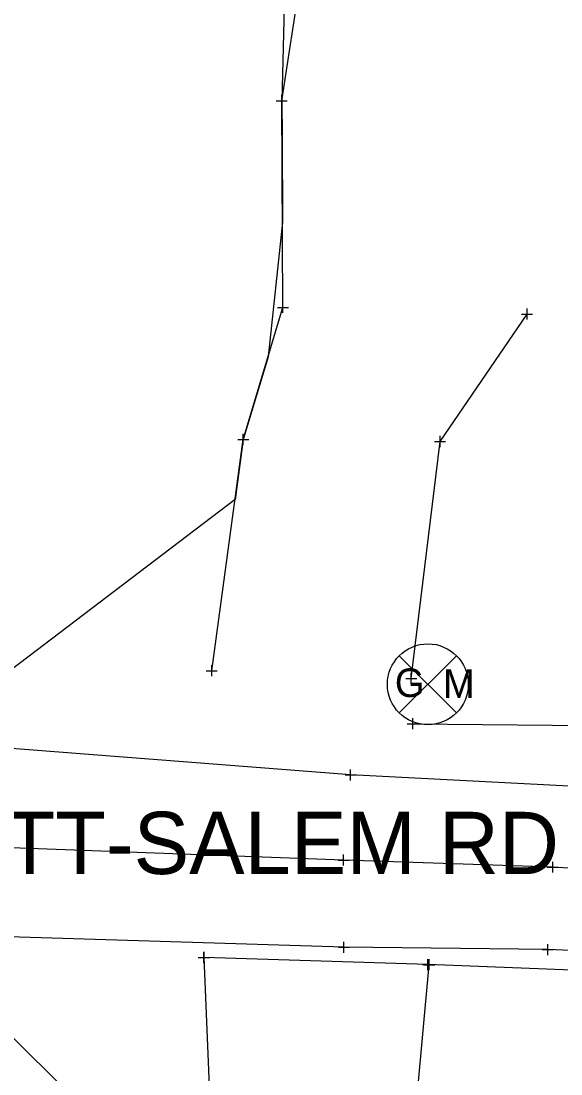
# Model space of a CAD drawing. Extents: x -1 to 1157254, y -1 to 2021979.
# Drawn here: x 1150264.3 to 1150326.7, y 2020191.5 to 2020313.4 of the extents above; entities that cross this region are included whole.
import ezdxf

# ---------------------------------------------------------------- set-up
doc = ezdxf.new("R2010")
doc.units = 0
for name, color, linetype in [('S_BUILDING_ANNOT', 7, 'Continuous'), ('S_CAL_CORNER_ANNOT', 7, 'Continuous'), ('S_CTL_TABLE', 7, 'Continuous'), ('S_DRIVEWAY_ANNOT', 7, 'Continuous'), ('S_EDGE_BITUMINOUS_ANNOT', 7, 'Continuous'), ('S_EDGE_CONCRETE', 7, 'Continuous'), ('S_EDGE_CONCRETE_ANNOT', 7, 'Continuous'), ('S_GAS_PUMP_ISLAND_ANNOT', 7, 'Continuous'), ('S_GATE', 7, 'Continuous')]:
    doc.layers.add(name, color=color, linetype=linetype)

msp = doc.modelspace()

# ---------------------------------------------------------------- linework, layer by layer
at = {"layer": 'S_BUILDING_ANNOT'}
for p, q in [((1150309.59, 2020231.42), (1150309.59, 2020232.69)), ((1150308.96, 2020232.06), (1150310.23, 2020232.06)), ((1150309.59, 2020232.06), (1150309.59, 2020232.06)), ((1150301.77, 2020226.14), (1150303.04, 2020226.14)), ((1150302.4, 2020225.5), (1150302.4, 2020226.77)), ((1150302.4, 2020226.14), (1150302.4, 2020226.14)), ((1150301.59, 2020215.63), (1150301.59, 2020216.91)), ((1150300.95, 2020216.27), (1150302.23, 2020216.27)), ((1150301.59, 2020216.27), (1150301.59, 2020216.27)), ((1150325.15, 2020215.45), (1150326.42, 2020215.46)), ((1150325.79, 2020214.82), (1150325.79, 2020216.09)), ((1150325.79, 2020215.45), (1150325.79, 2020215.45)), ((1150301.63, 2020205.55), (1150301.63, 2020206.82)), ((1150301, 2020206.19), (1150302.27, 2020206.19)), ((1150301.63, 2020206.19), (1150301.63, 2020206.19)), ((1150324.58, 2020205.91), (1150325.86, 2020205.91)), ((1150325.22, 2020205.27), (1150325.22, 2020206.55)), ((1150325.22, 2020205.91), (1150325.22, 2020205.91))]:
    msp.add_line(p, q, dxfattribs=at)
at = {"layer": 'S_CAL_CORNER_ANNOT'}
for p, q in [((1150308.03, 2020233.31), (1150314.65, 2020239.92)), ((1150308.03, 2020239.92), (1150314.65, 2020233.31))]:
    msp.add_line(p, q, dxfattribs=at)
msp.add_circle((1150311.34, 2020236.62), 4.68, dxfattribs=at)
at = {"layer": 'S_CTL_TABLE'}
for p, q in [((1150293.8, 2020304.15), (1150295.07, 2020304.15)), ((1150294.44, 2020303.52), (1150294.43, 2020304.79)), ((1150294.44, 2020304.15), (1150294.44, 2020304.15)), ((1150293.92, 2020280.24), (1150295.2, 2020280.24)), ((1150294.56, 2020279.6), (1150294.56, 2020280.87)), ((1150294.56, 2020280.24), (1150294.56, 2020280.24)), ((1150322.82, 2020278.83), (1150322.82, 2020280.1)), ((1150322.18, 2020279.47), (1150323.45, 2020279.47)), ((1150322.82, 2020279.47), (1150322.82, 2020279.47)), ((1150289.97, 2020264.32), (1150289.97, 2020265.59)), ((1150312.75, 2020264.08), (1150312.75, 2020265.36)), ((1150289.33, 2020264.95), (1150290.61, 2020264.96)), ((1150289.97, 2020264.95), (1150289.97, 2020264.95)), ((1150312.11, 2020264.72), (1150313.38, 2020264.72)), ((1150312.75, 2020264.72), (1150312.75, 2020264.72)), ((1150286.32, 2020237.55), (1150286.32, 2020238.83)), ((1150285.68, 2020238.19), (1150286.95, 2020238.19)), ((1150286.32, 2020238.19), (1150286.32, 2020238.19)), ((1150308.79, 2020237.3), (1150310.06, 2020237.3)), ((1150309.42, 2020236.66), (1150309.42, 2020237.93)), ((1150309.42, 2020237.3), (1150309.42, 2020237.3)), ((1150285.41, 2020204.37), (1150285.41, 2020205.64)), ((1150285.45, 2020204.36), (1150285.45, 2020205.64)), ((1150284.77, 2020205), (1150286.05, 2020205)), ((1150284.81, 2020205), (1150286.09, 2020205)), ((1150285.41, 2020205), (1150285.41, 2020205)), ((1150285.45, 2020205), (1150285.45, 2020205)), ((1150310.7, 2020204.19), (1150311.97, 2020204.19)), ((1150310.86, 2020204.17), (1150312.13, 2020204.17)), ((1150311.34, 2020203.55), (1150311.34, 2020204.82)), ((1150311.34, 2020204.19), (1150311.34, 2020204.19)), ((1150311.5, 2020203.54), (1150311.5, 2020204.81)), ((1150311.5, 2020204.17), (1150311.5, 2020204.17))]:
    msp.add_line(p, q, dxfattribs=at)
at = {"layer": 'S_DRIVEWAY_ANNOT'}
msp.add_lwpolyline([(1150309.59, 2020232.06), (1150333.79, 2020231.81), (1150349.29, 2020230.87), (1150361.39, 2020229.43), (1150366.44, 2020229.39), (1150370.6, 2020230.22), (1150372.42, 2020234.01), (1150372.87, 2020238.78), (1150372.93, 2020241.26), (1150374.09, 2020242.37)], dxfattribs=at)
at = {"layer": 'S_EDGE_BITUMINOUS_ANNOT'}
for points in [[(1150286.32, 2020238.19), (1150289.97, 2020264.95), (1150294.56, 2020280.24), (1150294.44, 2020304.15), (1150296.65, 2020318.45), (1150295.02, 2020327.49), (1150295.26, 2020352.35), (1150299.84, 2020383.5), (1150300.31, 2020434.18)], [(1150309.42, 2020237.3), (1150312.75, 2020264.72), (1150322.82, 2020279.47)], [(1150357.45, 2020078.92), (1150358.97, 2020104.94), (1150359.07, 2020139.54), (1150360.26, 2020173.71), (1150361.63, 2020194.38), (1150338.79, 2020203.11), (1150311.34, 2020204.19), (1150285.41, 2020205)], [(1150294.08, 2020068.33), (1150285.94, 2020139.4), (1150286.8, 2020172.42), (1150285.45, 2020205)], [(1150317.68, 2020072.66), (1150318.52, 2020104.05), (1150310.55, 2020139.79), (1150308.7, 2020173.74), (1150311.5, 2020204.17)]]:
    msp.add_lwpolyline(points, dxfattribs=at)
at = {"layer": 'S_EDGE_CONCRETE'}
for points in [[(1150377.6, 2020232.89), (1150373.6, 2020227.53), (1150367.53, 2020224.48), (1150354.89, 2020224.17), (1150327.69, 2020224.84), (1150302.4, 2020226.14), (1150261.15, 2020229.35), (1150223.67, 2020228.92), (1150183.34, 2020230.29), (1150144.2, 2020231.28), (1150095.62, 2020233.53)], [(1150376.1, 2020175.29), (1150374.34, 2020182.07), (1150369.84, 2020188.52), (1150363.61, 2020195.61), (1150353.92, 2020202.39), (1150340.22, 2020205.26), (1150325.22, 2020205.91), (1150301.63, 2020206.19), (1150261.53, 2020207.42), (1150221.68, 2020207.35), (1150183.11, 2020208.06), (1150141.65, 2020210.13), (1150094.5, 2020210.78)]]:
    msp.add_lwpolyline(points, dxfattribs=at)
at = {"layer": 'S_EDGE_CONCRETE_ANNOT'}
msp.add_lwpolyline([(1150376.96, 2020213.82), (1150360.59, 2020213.97), (1150340.53, 2020214.48), (1150325.79, 2020215.45), (1150301.59, 2020216.27), (1150262.07, 2020217.72), (1150223.53, 2020218.58), (1150183.21, 2020219.5), (1150142.56, 2020221.06), (1150094.65, 2020222.47)], dxfattribs=at)
at = {"layer": 'S_GAS_PUMP_ISLAND_ANNOT'}
for points in [[(1150420.96, 2020435.87), (1150379.51, 2020433.59), (1150368.33, 2020432.16), (1150321.84, 2020435.66), (1150300.31, 2020434.18), (1150300.3, 2020433.49), (1150300.21, 2020423.49), (1150300.12, 2020413.5), (1150300.02, 2020403.5), (1150299.93, 2020393.5), (1150298.17, 2020372.13), (1150296.71, 2020362.24), (1150295.26, 2020352.35), (1150295.21, 2020347.48), (1150295.12, 2020337.49), (1150295.02, 2020327.49), (1150294.44, 2020304.15), (1150294.46, 2020299.95), (1150294.51, 2020290.09), (1150292.85, 2020274.53), (1150289.97, 2020264.95), (1150289.02, 2020258), (1150251.15, 2020229.23)], [(1150251.53, 2020207.4), (1150286.8, 2020172.42), (1150286.73, 2020169.39), (1150286.46, 2020159.39), (1150286.2, 2020149.4), (1150285.94, 2020139.4), (1150286.12, 2020137.87), (1150287.26, 2020127.94), (1150288.39, 2020118), (1150289.53, 2020108.07), (1150290.67, 2020098.13), (1150262.09, 2020060.03)]]:
    msp.add_lwpolyline(points, dxfattribs=at)

# ---------------------------------------------------------------- texts
at = {"layer": 'S_CAL_CORNER_ANNOT'}
for s, p in [('G', (1150307.52, 2020235.15)), ('M', (1150313.09, 2020235.05))]:
    msp.add_text(s, height=3.3, dxfattribs=at).set_placement(p)
at = {"layer": 'S_GATE'}
msp.add_text('SCOTT-SALEM RD NO CUS', height=7.2, dxfattribs=at).set_placement((1150241.46, 2020214.66))

doc.saveas('drawing.dxf')
